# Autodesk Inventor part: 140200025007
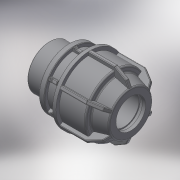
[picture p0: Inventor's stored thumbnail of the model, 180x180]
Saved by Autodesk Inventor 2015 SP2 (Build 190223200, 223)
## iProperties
Created: 2017-08
Part Number: 140200025007
Material: Generic
Description: PLASSON L.14 MALE ADAPTOR (SILVER) 25-3/4''
Document SubType Name: Modeling
Designer: KIM
Density: 1 g/cm^3
Appearance: Default
Author: KIM
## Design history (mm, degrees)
derived "140200.ipt"
feature "Solid1::140200.ipt"
tag "TaggingFeature1"
body "Solid1"
other parameters: "d1" = 25, "d2" = 54, "d4" = 15 deg, "d5" = 35.64, "d6" = 11.7612, "d16" = 25.5, "d17" = 2.7, "d18" = 75, "d19" = 5.1, "d21" = 5.1, "d22" = 31.7292, "d24" = 2.7, "d25" = 45, "d26" = 37.5, "d27" = 2.7, "d28" = 135 deg, "d29" = 1.62, "d31" = 1.25, "d44" = 0.5, "d45" = 0.75, "d46" = 150 deg, "d49" = 2.5, "d50" = 0, "d51" = 1.5, "d52" = 1, "d53" = 45 deg, "d54" = 21, "d55" = 6.3, "d56" = 2.5, "d57" = 0, "d58" = 0.75, "d59" = 0.5, "d61" = 360 deg, "d63" = 26.441, "d65" = 17, "d66" = 35.69535, "d_" = 25, "R_" = 26.441, "H_" = 75, "l_" = 54, "l_2" = 17
